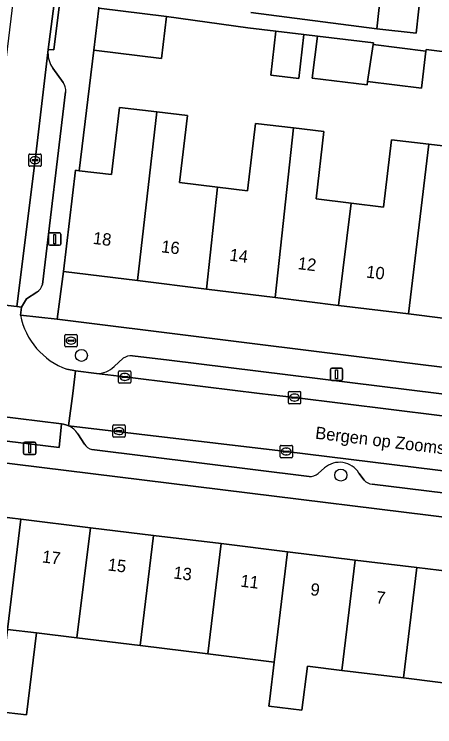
# Model space of a CAD drawing. Extents: x 158086 to 159499, y 382904 to 383981.
# Drawn here: x 158502.2 to 158536.4, y 383222.9 to 383280.8 of the extents above; entities that cross this region are included whole.
import ezdxf

# ---------------------------------------------------------------- set-up
doc = ezdxf.new("R2010")
doc.units = 0
for name, color, linetype in [('IMGEO_Boom', 7, 'Continuous'), ('IMGEO_Brandkraan', 7, 'Continuous'), ('IMGEO_Erf', 7, 'Continuous'), ('IMGEO_Kolk', 7, 'Continuous'), ('IMGEO_Lichtmast', 7, 'Continuous'), ('IMGEO_Muur', 7, 'Continuous'), ('IMGEO_Openbare_ruimte_label', 7, 'Continuous'), ('IMGEO_Pand', 7, 'Continuous'), ('IMGEO_Pand_nummerreeks', 7, 'Continuous'), ('IMGEO_Parkeervlak_open', 7, 'Continuous'), ('IMGEO_Rijbaan_lokaal_open', 7, 'Continuous'), ('IMGEO_Voetpad_open', 7, 'Continuous')]:
    doc.layers.add(name, color=color, linetype=linetype)

msp = doc.modelspace()

# ---------------------------------------------------------------- linework, layer by layer
at = {"layer": 'IMGEO_Boom'}
for centre in [(158507.643, 383253.088), (158528.736, 383243.352)]:
    msp.add_circle(centre, 0.489, dxfattribs=at)
at = {"layer": 'IMGEO_Brandkraan'}
for p, q in [((158506.293, 383253.861), (158506.293, 383254.713)), ((158506.368, 383254.787), (158507.22, 383254.787)), ((158507.294, 383254.713), (158507.294, 383253.861)), ((158506.552, 383254.281), (158506.552, 383254.293)), ((158506.99, 383254.244), (158506.592, 383254.244)), ((158506.595, 383254.33), (158506.993, 383254.33)), ((158506.781, 383254.567), (158506.806, 383254.567)), ((158507.036, 383254.293), (158507.036, 383254.281)), ((158507.22, 383253.787), (158506.368, 383253.787)), ((158506.804, 383254.007), (158506.779, 383254.007))]:
    msp.add_line(p, q, dxfattribs=at)
for points in [[(158506.293, 383253.861), (158506.293, 383254.713)], [(158506.368, 383254.787), (158507.22, 383254.787)], [(158507.294, 383254.713), (158507.294, 383253.861)], [(158507.22, 383253.787), (158506.368, 383253.787)]]:
    msp.add_lwpolyline(points, dxfattribs=at)
for centre, radius, start, end in [((158506.37, 383254.711), 0.0765, 91.55205, 178.44795), ((158506.37, 383254.711), 0.0765, 91.55205, 178.44795), ((158507.218, 383254.711), 0.0765, 1.55205, 88.44795), ((158507.218, 383254.711), 0.0765, 1.55205, 88.44795), ((158506.592, 383254.29), 0.0403, 85.87752, 175.75265), ((158506.589, 383254.28), 0.0366, 178.93798, 274.71019), ((158506.993, 383254.287), 0.043, 264.86636, 352.45326), ((158506.997, 383254.292), 0.0386, 1.73085, 96.63898), ((158506.37, 383253.863), 0.0765, 181.55205, 268.44795), ((158506.37, 383253.863), 0.0765, 181.55205, 268.44795), ((158507.218, 383253.863), 0.0765, 271.55205, 358.44795), ((158507.218, 383253.863), 0.0765, 271.55205, 358.44795)]:
    msp.add_arc(centre, radius, start, end, dxfattribs=at)
for centre, major_axis, ratio, start_param, end_param in [((158506.78, 383254.287), (-0.387, 0.002), 0.722429, 4.712389, 7.853982), ((158506.805, 383254.287), (-0.39, 0.002), 0.717154, 1.570796, 4.712389)]:
    msp.add_ellipse(centre, major_axis=major_axis, ratio=ratio, start_param=start_param, end_param=end_param, dxfattribs=at)
at = {"layer": 'IMGEO_Erf'}
for points in [[(158521.412, 383280.985), (158531.662, 383279.663), (158532.239, 383284.915)], [(158539.134, 383277.539), (158535.677, 383277.974), (158535.661, 383277.846), (158535.287, 383274.821), (158530.915, 383275.361), (158530.874, 383275.085), (158526.416, 383275.634), (158526.839, 383279.064), (158525.723, 383279.202), (158525.309, 383275.617), (158523.04, 383275.879), (158523.453, 383279.464), (158521.184, 383279.726), (158514.552, 383280.667), (158514.141, 383277.252), (158508.652, 383277.913), (158507.469, 383268.111), (158510.085, 383267.796), (158510.743, 383273.257), (158513.77, 383272.893), (158516.274, 383272.591), (158515.618, 383267.153), (158518.702, 383266.781), (158521.148, 383266.486), (158521.809, 383271.957), (158524.878, 383271.588), (158527.351, 383271.291), (158526.723, 383265.818), (158529.577, 383265.474), (158532.194, 383265.159), (158532.854, 383270.63), (158535.898, 383270.264), (158538.416, 383269.961)], [(158539.607, 383255.796), (158534.234, 383256.458), (158528.551, 383257.159), (158523.4, 383257.793), (158517.822, 383258.481), (158512.21, 383259.173), (158506.181, 383259.916), (158505.675, 383256.031), (158554.129, 383250)], [(158554.304, 383221.99), (158557.145, 383237.463), (158500, 383244.504)], [(158500, 383240.091), (158502.71, 383239.761), (158508.368, 383239.07), (158513.498, 383238.445), (158518.992, 383237.775), (158524.404, 383237.115), (158529.904, 383236.444), (158534.922, 383235.832), (158540.289, 383235.178)], [(158540.968, 383221.862), (158541.465, 383225.918), (158539.205, 383226.195), (158533.838, 383226.852), (158528.82, 383227.467), (158526.013, 383227.811), (158525.575, 383224.232), (158522.887, 383224.556), (158522.96, 383225.163), (158523.32, 383228.141), (158517.91, 383228.804), (158512.415, 383229.477), (158507.275, 383230.106), (158503.994, 383230.508), (158503.18, 383223.84), (158500.802, 383224.131), (158501.616, 383230.799), (158500, 383230.997), (158496.419, 383231.436), (158494.542, 383218.82)]]:
    msp.add_lwpolyline(points, dxfattribs=at)
at = {"layer": 'IMGEO_Kolk'}
for p, q in [((158503.368, 383268.543), (158503.368, 383269.395)), ((158503.443, 383269.469), (158504.295, 383269.469)), ((158503.856, 383269.249), (158503.881, 383269.249)), ((158504.369, 383269.395), (158504.369, 383268.543)), ((158503.627, 383268.963), (158503.627, 383268.975)), ((158504.065, 383268.926), (158503.667, 383268.926)), ((158503.67, 383269.012), (158504.068, 383269.012)), ((158503.879, 383268.689), (158503.854, 383268.689)), ((158504.111, 383268.975), (158504.111, 383268.963)), ((158504.295, 383268.469), (158503.443, 383268.469)), ((158510.666, 383250.908), (158510.666, 383251.76)), ((158510.741, 383251.834), (158511.593, 383251.834)), ((158511.667, 383251.76), (158511.667, 383250.908)), ((158510.925, 383251.328), (158510.925, 383251.34)), ((158511.363, 383251.291), (158510.965, 383251.291)), ((158510.968, 383251.377), (158511.366, 383251.377)), ((158511.154, 383251.614), (158511.179, 383251.614)), ((158511.409, 383251.34), (158511.409, 383251.328)), ((158511.593, 383250.834), (158510.741, 383250.834)), ((158511.177, 383251.054), (158511.152, 383251.054)), ((158524.469, 383249.232), (158524.469, 383250.084)), ((158524.544, 383250.158), (158525.396, 383250.158)), ((158525.47, 383250.084), (158525.47, 383249.232)), ((158524.728, 383249.652), (158524.728, 383249.664)), ((158525.166, 383249.615), (158524.768, 383249.615)), ((158524.771, 383249.701), (158525.169, 383249.701)), ((158524.957, 383249.938), (158524.982, 383249.938)), ((158525.212, 383249.664), (158525.212, 383249.652)), ((158525.396, 383249.158), (158524.544, 383249.158)), ((158524.98, 383249.378), (158524.955, 383249.378)), ((158510.19, 383246.511), (158510.19, 383247.363)), ((158510.265, 383247.437), (158511.117, 383247.437)), ((158510.678, 383247.217), (158510.703, 383247.217)), ((158511.191, 383247.363), (158511.191, 383246.511)), ((158510.449, 383246.931), (158510.449, 383246.943)), ((158510.887, 383246.894), (158510.489, 383246.894)), ((158510.492, 383246.98), (158510.89, 383246.98)), ((158510.701, 383246.657), (158510.676, 383246.657)), ((158510.933, 383246.943), (158510.933, 383246.931)), ((158511.117, 383246.437), (158510.265, 383246.437)), ((158523.799, 383244.842), (158523.799, 383245.694)), ((158523.874, 383245.768), (158524.726, 383245.768)), ((158524.287, 383245.548), (158524.312, 383245.548)), ((158524.8, 383245.694), (158524.8, 383244.842)), ((158524.058, 383245.262), (158524.058, 383245.274)), ((158524.496, 383245.225), (158524.098, 383245.225)), ((158524.101, 383245.311), (158524.499, 383245.311)), ((158524.31, 383244.988), (158524.285, 383244.988)), ((158524.542, 383245.274), (158524.542, 383245.262)), ((158524.726, 383244.768), (158523.874, 383244.768))]:
    msp.add_line(p, q, dxfattribs=at)
for points in [[(158503.368, 383268.543), (158503.368, 383269.395)], [(158503.443, 383269.469), (158504.295, 383269.469)], [(158504.369, 383269.395), (158504.369, 383268.543)], [(158504.295, 383268.469), (158503.443, 383268.469)], [(158510.666, 383250.908), (158510.666, 383251.76)], [(158510.741, 383251.834), (158511.593, 383251.834)], [(158511.667, 383251.76), (158511.667, 383250.908)], [(158511.593, 383250.834), (158510.741, 383250.834)], [(158524.469, 383249.232), (158524.469, 383250.084)], [(158524.544, 383250.158), (158525.396, 383250.158)], [(158525.47, 383250.084), (158525.47, 383249.232)], [(158525.396, 383249.158), (158524.544, 383249.158)], [(158510.19, 383246.511), (158510.19, 383247.363)], [(158510.265, 383247.437), (158511.117, 383247.437)], [(158511.191, 383247.363), (158511.191, 383246.511)], [(158511.117, 383246.437), (158510.265, 383246.437)], [(158523.799, 383244.842), (158523.799, 383245.694)], [(158523.874, 383245.768), (158524.726, 383245.768)], [(158524.8, 383245.694), (158524.8, 383244.842)], [(158524.726, 383244.768), (158523.874, 383244.768)]]:
    msp.add_lwpolyline(points, dxfattribs=at)
for centre, radius, start, end in [((158503.445, 383269.393), 0.0765, 91.55205, 178.44795), ((158503.445, 383269.393), 0.0765, 91.55205, 178.44795), ((158504.293, 383269.393), 0.0765, 1.55205, 88.44795), ((158504.293, 383269.393), 0.0765, 1.55205, 88.44795), ((158503.667, 383268.972), 0.0403, 85.87752, 175.75265), ((158503.664, 383268.962), 0.0366, 178.93798, 274.71019), ((158504.068, 383268.969), 0.043, 264.86636, 352.45326), ((158504.072, 383268.974), 0.0386, 1.73085, 96.63898), ((158503.445, 383268.545), 0.0765, 181.55205, 268.44795), ((158503.445, 383268.545), 0.0765, 181.55205, 268.44795), ((158504.293, 383268.545), 0.0765, 271.55205, 358.44795), ((158504.293, 383268.545), 0.0765, 271.55205, 358.44795), ((158510.743, 383251.758), 0.0765, 91.55205, 178.44795), ((158510.743, 383251.758), 0.0765, 91.55205, 178.44795), ((158511.591, 383251.758), 0.0765, 1.55205, 88.44795), ((158511.591, 383251.758), 0.0765, 1.55205, 88.44795), ((158510.965, 383251.337), 0.0403, 85.87752, 175.75265), ((158510.962, 383251.327), 0.0366, 178.93798, 274.71019), ((158511.366, 383251.334), 0.043, 264.86636, 352.45326), ((158511.37, 383251.339), 0.0386, 1.73085, 96.63898), ((158510.743, 383250.91), 0.0765, 181.55205, 268.44795), ((158510.743, 383250.91), 0.0765, 181.55205, 268.44795), ((158511.591, 383250.91), 0.0765, 271.55205, 358.44795), ((158511.591, 383250.91), 0.0765, 271.55205, 358.44795), ((158524.546, 383250.082), 0.0765, 91.55205, 178.44795), ((158524.546, 383250.082), 0.0765, 91.55205, 178.44795), ((158525.394, 383250.082), 0.0765, 1.55205, 88.44795), ((158525.394, 383250.082), 0.0765, 1.55205, 88.44795), ((158524.768, 383249.661), 0.0403, 85.87752, 175.75265), ((158524.765, 383249.651), 0.0366, 178.93798, 274.71019), ((158525.169, 383249.658), 0.043, 264.86636, 352.45326), ((158525.173, 383249.663), 0.0386, 1.73085, 96.63898), ((158524.546, 383249.234), 0.0765, 181.55205, 268.44795), ((158524.546, 383249.234), 0.0765, 181.55205, 268.44795), ((158525.394, 383249.234), 0.0765, 271.55205, 358.44795), ((158525.394, 383249.234), 0.0765, 271.55205, 358.44795), ((158510.267, 383247.361), 0.0765, 91.55205, 178.44795), ((158510.267, 383247.361), 0.0765, 91.55205, 178.44795), ((158511.115, 383247.361), 0.0765, 1.55205, 88.44795), ((158511.115, 383247.361), 0.0765, 1.55205, 88.44795), ((158510.489, 383246.94), 0.0403, 85.87752, 175.75265), ((158510.486, 383246.93), 0.0366, 178.93798, 274.71019), ((158510.89, 383246.937), 0.043, 264.86636, 352.45326), ((158510.894, 383246.942), 0.0386, 1.73085, 96.63898), ((158510.267, 383246.513), 0.0765, 181.55205, 268.44795), ((158510.267, 383246.513), 0.0765, 181.55205, 268.44795), ((158511.115, 383246.513), 0.0765, 271.55205, 358.44795), ((158511.115, 383246.513), 0.0765, 271.55205, 358.44795), ((158523.876, 383245.692), 0.0765, 91.55205, 178.44795), ((158523.876, 383245.692), 0.0765, 91.55205, 178.44795), ((158524.724, 383245.692), 0.0765, 1.55205, 88.44795), ((158524.724, 383245.692), 0.0765, 1.55205, 88.44795), ((158523.876, 383244.844), 0.0765, 181.55205, 268.44795), ((158523.876, 383244.844), 0.0765, 181.55205, 268.44795), ((158524.098, 383245.271), 0.0403, 85.87752, 175.75265), ((158524.095, 383245.261), 0.0366, 178.93798, 274.71019), ((158524.499, 383245.268), 0.043, 264.86636, 352.45326), ((158524.503, 383245.273), 0.0386, 1.73085, 96.63898), ((158524.724, 383244.844), 0.0765, 271.55205, 358.44795), ((158524.724, 383244.844), 0.0765, 271.55205, 358.44795)]:
    msp.add_arc(centre, radius, start, end, dxfattribs=at)
for centre, major_axis, ratio, start_param, end_param in [((158503.855, 383268.969), (-0.387, 0.002), 0.722429, 4.712389, 7.853982), ((158503.88, 383268.969), (-0.39, 0.002), 0.717154, 1.570796, 4.712389), ((158511.153, 383251.334), (-0.387, 0.002), 0.722429, 4.712389, 7.853982), ((158511.178, 383251.334), (-0.39, 0.002), 0.717154, 1.570796, 4.712389), ((158524.956, 383249.658), (-0.387, 0.002), 0.722429, 4.712389, 7.853982), ((158524.981, 383249.658), (-0.39, 0.002), 0.717154, 1.570796, 4.712389), ((158510.677, 383246.937), (-0.387, 0.002), 0.722429, 4.712389, 7.853982), ((158510.702, 383246.937), (-0.39, 0.002), 0.717154, 1.570796, 4.712389), ((158524.286, 383245.268), (-0.387, 0.002), 0.722429, 4.712389, 7.853982), ((158524.311, 383245.268), (-0.39, 0.002), 0.717154, 1.570796, 4.712389)]:
    msp.add_ellipse(centre, major_axis=major_axis, ratio=ratio, start_param=start_param, end_param=end_param, dxfattribs=at)
at = {"layer": 'IMGEO_Lichtmast'}
for p, q in [((158504.97, 383262.145), (158504.97, 383262.945)), ((158504.97, 383262.945), (158504.97, 383262.145)), ((158505.07, 383263.045), (158505.86, 383263.045)), ((158505.86, 383263.045), (158505.07, 383263.045)), ((158505.96, 383262.945), (158505.96, 383262.145)), ((158505.96, 383262.145), (158505.96, 383262.945)), ((158505.86, 383262.045), (158505.07, 383262.045)), ((158505.07, 383262.045), (158505.86, 383262.045)), ((158527.894, 383251.147), (158527.894, 383251.947)), ((158527.894, 383251.947), (158527.894, 383251.147)), ((158527.994, 383252.047), (158528.784, 383252.047)), ((158528.784, 383252.047), (158527.994, 383252.047)), ((158528.884, 383251.947), (158528.884, 383251.147)), ((158528.884, 383251.147), (158528.884, 383251.947)), ((158528.784, 383251.047), (158527.994, 383251.047)), ((158527.994, 383251.047), (158528.784, 383251.047)), ((158503.037, 383246.034), (158503.827, 383246.034)), ((158503.827, 383246.034), (158503.037, 383246.034)), ((158502.937, 383245.134), (158502.937, 383245.934)), ((158502.937, 383245.934), (158502.937, 383245.134)), ((158503.927, 383245.934), (158503.927, 383245.134)), ((158503.927, 383245.134), (158503.927, 383245.934)), ((158503.827, 383245.034), (158503.037, 383245.034)), ((158503.037, 383245.034), (158503.827, 383245.034))]:
    msp.add_line(p, q, dxfattribs=at)
for points in [[(158505.39, 383262.92), (158505.54, 383262.92), (158505.54, 383262.17), (158505.39, 383262.17), (158505.39, 383262.92)], [(158528.314, 383251.922), (158528.464, 383251.922), (158528.464, 383251.172), (158528.314, 383251.172), (158528.314, 383251.922)], [(158503.357, 383245.909), (158503.507, 383245.909), (158503.507, 383245.159), (158503.357, 383245.159), (158503.357, 383245.909)]]:
    msp.add_lwpolyline(points, dxfattribs=at)
for centre, start, end in [((158505.07, 383262.945), 90, 180), ((158505.07, 383262.945), 90, 180), ((158505.86, 383262.945), 0, 90), ((158505.86, 383262.945), 360, 90), ((158505.07, 383262.145), 180, 270), ((158505.07, 383262.145), 180, 270), ((158505.86, 383262.145), 270, 0), ((158505.86, 383262.145), 270, 0), ((158527.994, 383251.947), 90, 180), ((158527.994, 383251.947), 90, 180), ((158528.784, 383251.947), 0, 90), ((158528.784, 383251.947), 360, 90), ((158527.994, 383251.147), 180, 270), ((158527.994, 383251.147), 180, 270), ((158528.784, 383251.147), 270, 0), ((158528.784, 383251.147), 270, 0), ((158503.037, 383245.934), 90, 180), ((158503.037, 383245.934), 90, 180), ((158503.827, 383245.934), 0, 90), ((158503.827, 383245.934), 360, 90), ((158503.037, 383245.134), 180, 270), ((158503.037, 383245.134), 180, 270), ((158503.827, 383245.134), 270, 0), ((158503.827, 383245.134), 270, 0)]:
    msp.add_arc(centre, 0.1, start, end, dxfattribs=at)
at = {"layer": 'IMGEO_Muur'}
msp.add_lwpolyline([(158507.469, 383268.111), (158508.652, 383277.913)], dxfattribs=at)
at = {"layer": 'IMGEO_Pand'}
for points in [[(158535.439, 383284.53), (158532.239, 383284.915), (158531.662, 383279.663), (158534.866, 383279.311)], [(158508.652, 383277.913), (158514.141, 383277.252), (158514.552, 383280.667), (158509.061, 383281.327)], [(158525.723, 383279.202), (158523.453, 383279.464), (158523.04, 383275.879), (158525.309, 383275.617)], [(158531.368, 383278.375), (158531.387, 383278.503), (158526.839, 383279.064), (158526.416, 383275.634), (158530.874, 383275.085), (158530.915, 383275.361)], [(158535.661, 383277.846), (158531.368, 383278.375), (158530.915, 383275.361), (158535.287, 383274.821)], [(158513.77, 383272.893), (158510.743, 383273.257), (158510.085, 383267.796), (158507.469, 383268.111), (158507.166, 383268.147), (158506.181, 383259.916), (158512.21, 383259.173)], [(158513.77, 383272.893), (158512.21, 383259.173), (158517.822, 383258.481), (158518.702, 383266.781), (158515.618, 383267.153), (158516.274, 383272.591)], [(158518.702, 383266.781), (158517.822, 383258.481), (158523.4, 383257.793), (158524.878, 383271.588), (158521.809, 383271.957), (158521.148, 383266.486)], [(158524.878, 383271.588), (158523.4, 383257.793), (158528.551, 383257.159), (158529.577, 383265.474), (158526.723, 383265.818), (158527.351, 383271.291)], [(158534.234, 383256.458), (158535.898, 383270.264), (158532.854, 383270.63), (158532.194, 383265.159), (158529.577, 383265.474), (158528.551, 383257.159)], [(158534.234, 383256.458), (158539.607, 383255.796), (158540.63, 383264.283), (158537.773, 383264.627), (158538.416, 383269.961), (158535.898, 383270.264)], [(158501.616, 383230.799), (158502.71, 383239.761), (158500, 383240.091), (158497.517, 383240.394), (158496.909, 383235.432), (158496.419, 383231.436), (158500, 383230.997)], [(158508.368, 383239.07), (158502.71, 383239.761), (158501.616, 383230.799), (158503.994, 383230.508), (158507.275, 383230.106)], [(158513.498, 383238.445), (158508.368, 383239.07), (158507.275, 383230.106), (158512.415, 383229.477)], [(158518.992, 383237.775), (158513.498, 383238.445), (158512.415, 383229.477), (158517.91, 383228.804)], [(158524.404, 383237.115), (158518.992, 383237.775), (158517.91, 383228.804), (158523.32, 383228.141)], [(158524.404, 383237.115), (158523.32, 383228.141), (158522.96, 383225.163), (158522.887, 383224.556), (158525.575, 383224.232), (158526.013, 383227.811), (158528.82, 383227.467), (158529.904, 383236.444)], [(158528.82, 383227.467), (158533.838, 383226.852), (158534.922, 383235.832), (158529.904, 383236.444)], [(158540.289, 383235.178), (158534.922, 383235.832), (158533.838, 383226.852), (158539.205, 383226.195)], [(158503.994, 383230.508), (158501.616, 383230.799), (158500.802, 383224.131), (158503.18, 383223.84)]]:
    msp.add_lwpolyline(points, close=True, dxfattribs=at)
at = {"layer": 'IMGEO_Parkeervlak_open'}
for points in [[(158504.919, 383277.738), (158503.867, 383268.969), (158502.387, 383257.071), (158502.767, 383257.007), (158503.182, 383257.687), (158504.006, 383258.231)], [(158506.155, 383275.275), (158505.305, 383276.458)], [(158504.475, 383258.868), (158506.359, 383274.53)], [(158555.506, 383247.692), (158536.699, 383250), (158514.765, 383252.707), (158511.786, 383253.063)], [(158511.049, 383252.854), (158510.301, 383252.191)], [(158508.865, 383251.607), (158511.166, 383251.332), (158515.542, 383250.802), (158522.118, 383250), (158524.966, 383249.656), (158540.697, 383247.714), (158555.572, 383245.902), (158556.395, 383245.816), (158557.139, 383245.805), (158558.233, 383245.857)], [(158556.058, 383241.376), (158552.411, 383241.836), (158539.945, 383243.351), (158524.296, 383245.269), (158506.597, 383247.359)], [(158507.337, 383246.712), (158507.882, 383245.88)], [(158508.498, 383245.426), (158526.169, 383243.244)], [(158526.888, 383243.475), (158527.415, 383243.936)], [(158530.209, 383243.519), (158530.624, 383242.952)], [(158531.288, 383242.615), (158553.149, 383239.93)]]:
    msp.add_lwpolyline(points, dxfattribs=at)
msp.add_lwpolyline([(158500.701, 383248.175), (158500.466, 383246.258), (158505.834, 383245.585), (158506.016, 383247.517)], close=True, dxfattribs=at)
for centre, radius, start, end in [((158507.176, 383277.721), 2.257, 179.55691, 214.00577), ((158505.345, 383274.653), 1.022, 353.09927, 37.52807), ((158503.416, 383259.157), 1.098, 302.52493, 344.74933), ((158511.738, 383251.827), 1.237, 87.79846, 123.86631), ((158508.894, 383253.593), 1.986, 269.16303, 315.09867), ((158505.827, 383245.732), 1.8, 32.99209, 64.67992), ((158508.734, 383246.391), 0.994, 210.96501, 256.2536), ((158528.635, 383242.538), 1.855, 31.91502, 131.10769), ((158526.241, 383244.254), 1.012, 265.91249, 309.70981), ((158531.319, 383243.498), 0.883, 218.16489, 268.01678)]:
    msp.add_arc(centre, radius, start, end, dxfattribs=at)
at = {"layer": 'IMGEO_Rijbaan_lokaal_open'}
for points in [[(158508.301, 383305.403), (158509.745, 383316.595), (158509.706, 383316.881), (158506.35, 383317.307), (158501.59, 383277.987), (158501.13, 383274.174), (158501.094, 383273.877), (158500.55, 383269.368), (158500, 383264.965), (158499.527, 383261.181), (158499.061, 383257.447), (158500, 383257.341), (158502.387, 383257.071), (158503.867, 383268.969), (158504.919, 383277.738), (158504.939, 383277.962), (158505.411, 383281.727), (158505.455, 383282.096), (158506.001, 383286.653)], [(158506.597, 383247.359), (158524.296, 383245.269), (158539.945, 383243.351), (158552.411, 383241.836), (158556.058, 383241.376), (158557.654, 383241.196), (158557.763, 383241.156), (158558.62, 383245.875), (158558.233, 383245.857), (158557.139, 383245.805), (158556.395, 383245.816), (158555.572, 383245.902), (158540.697, 383247.714), (158524.966, 383249.656), (158522.118, 383250), (158515.542, 383250.802), (158511.166, 383251.332), (158508.865, 383251.607), (158507.162, 383251.821), (158506.931, 383250)]]:
    msp.add_lwpolyline(points, close=True, dxfattribs=at)
for points in [[(158502.696, 383256.359), (158502.767, 383257.007), (158502.387, 383257.071), (158500, 383257.341), (158499.061, 383257.447), (158498.978, 383256.786)], [(158494.856, 383253.33), (158494.213, 383253.454), (158493.75, 383250), (158493.623, 383249.052), (158494.387, 383248.956), (158499.805, 383248.286), (158500, 383248.262), (158500.701, 383248.175), (158506.016, 383247.517), (158506.181, 383247.495), (158506.466, 383247.402), (158506.597, 383247.359), (158506.931, 383250), (158507.162, 383251.821), (158506.466, 383251.965)]]:
    msp.add_lwpolyline(points, dxfattribs=at)
msp.add_arc((158508.393, 383257.433), 5.798, 190.67447, 250.58394, dxfattribs=at)
at = {"layer": 'IMGEO_Voetpad_open'}
for points in [[(158508.652, 383277.913), (158509.061, 383281.327), (158509.196, 383282.453), (158517.077, 383348.332), (158517.21, 383349.447), (158519.734, 383369.12), (158520.1, 383372.893), (158516.792, 383373.293)], [(158535.439, 383284.53), (158534.866, 383279.311), (158531.662, 383279.663), (158521.412, 383280.985)], [(158505.455, 383282.096), (158505.411, 383281.727), (158505.855, 383281.671), (158505.395, 383277.931), (158504.939, 383277.962), (158504.919, 383277.738)], [(158509.061, 383281.327), (158514.552, 383280.667), (158521.184, 383279.726), (158523.453, 383279.464), (158525.723, 383279.202), (158526.839, 383279.064), (158531.387, 383278.503), (158531.368, 383278.375), (158535.661, 383277.846), (158535.677, 383277.974), (158539.134, 383277.539), (158539.202, 383278.102), (158542.349, 383277.725), (158542.281, 383277.159), (158545.05, 383276.81), (158547.812, 383276.478), (158550.288, 383276.18), (158553.55, 383275.789), (158554.548, 383275.647), (158560.056, 383274.966), (158563.934, 383274.338)], [(158504.006, 383258.231), (158503.182, 383257.687), (158502.767, 383257.007), (158502.696, 383256.359), (158505.675, 383256.031), (158506.181, 383259.916), (158507.166, 383268.147), (158507.469, 383268.111), (158508.652, 383277.913)], [(158505.305, 383276.458), (158506.155, 383275.275)], [(158506.359, 383274.53), (158504.475, 383258.868)], [(158277.718, 383271.726), (158339.394, 383264.164), (158340.307, 383264.052), (158345.526, 383263.412), (158350.794, 383262.766), (158350.957, 383262.746), (158353.332, 383262.456), (158436.049, 383252.351), (158455.212, 383250), (158496.63, 383244.919), (158496.962, 383244.878), (158498.052, 383244.744), (158500, 383244.504), (158557.145, 383237.463), (158557.763, 383241.156), (158557.654, 383241.196), (158556.058, 383241.376)], [(158505.675, 383256.031), (158502.696, 383256.359)], [(158558.233, 383245.857), (158558.62, 383245.875), (158559.351, 383249.35), (158554.129, 383250), (158505.675, 383256.031)], [(158511.786, 383253.063), (158514.765, 383252.707), (158536.699, 383250), (158555.506, 383247.692)], [(158510.301, 383252.191), (158511.049, 383252.854)], [(158506.466, 383251.965), (158507.162, 383251.821), (158508.865, 383251.607)], [(158506.597, 383247.359), (158506.466, 383247.402), (158506.181, 383247.495), (158506.016, 383247.517), (158505.834, 383245.585), (158500.466, 383246.258), (158500.701, 383248.175), (158500, 383248.262), (158499.805, 383248.286), (158499.574, 383246.427), (158494.166, 383247.073), (158494.387, 383248.956)], [(158507.882, 383245.88), (158507.337, 383246.712)], [(158526.169, 383243.244), (158508.498, 383245.426)], [(158527.415, 383243.936), (158526.888, 383243.475)], [(158530.624, 383242.952), (158530.209, 383243.519)], [(158553.149, 383239.93), (158531.288, 383242.615)]]:
    msp.add_lwpolyline(points, dxfattribs=at)
msp.add_lwpolyline([(158505.411, 383281.727), (158504.939, 383277.962), (158505.395, 383277.931), (158505.855, 383281.671)], close=True, dxfattribs=at)
for centre, radius, start, end in [((158507.176, 383277.721), 2.257, 179.55691, 214.00577), ((158505.345, 383274.653), 1.022, 353.09927, 37.52807), ((158503.416, 383259.157), 1.098, 302.52493, 344.74933), ((158508.393, 383257.433), 5.798, 190.67447, 250.58394), ((158511.738, 383251.827), 1.237, 87.79846, 123.86631), ((158508.894, 383253.593), 1.986, 269.16303, 315.09867), ((158505.827, 383245.732), 1.8, 32.99209, 64.67992), ((158508.734, 383246.391), 0.994, 210.96501, 256.2536), ((158528.635, 383242.538), 1.855, 31.91502, 131.10769), ((158526.241, 383244.254), 1.012, 265.91249, 309.70981), ((158531.319, 383243.498), 0.883, 218.16489, 268.01678)]:
    msp.add_arc(centre, radius, start, end, dxfattribs=at)

# ---------------------------------------------------------------- texts
at = {"layer": 'IMGEO_Openbare_ruimte_label'}
msp.add_text('Bergen op Zoomstraat', height=1, rotation=353.05259, dxfattribs=at).set_placement((158526.616, 383246.32))
at = {"layer": 'IMGEO_Pand_nummerreeks'}
for s, rotation, p in [('18', 352.97289, (158508.539, 383262.164)), ('16', 352.97289, (158514.092, 383261.48)), ('14', 352.97289, (158519.647, 383260.795)), ('12', 352.97289, (158525.199, 383260.11)), ('10', 352.97289, (158530.761, 383259.425)), ('17', 353.04429, (158504.401, 383236.25)), ('15', 353.04429, (158509.741, 383235.599)), ('13', 353.04655, (158515.082, 383234.948)), ('11', 353.04655, (158520.535, 383234.282)), ('9', 353.04655, (158526.22, 383233.589)), ('7', 353.04655, (158531.561, 383232.938))]:
    msp.add_text(s, height=1, rotation=rotation, dxfattribs=at).set_placement(p)

doc.saveas('drawing.dxf')
